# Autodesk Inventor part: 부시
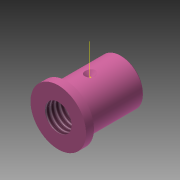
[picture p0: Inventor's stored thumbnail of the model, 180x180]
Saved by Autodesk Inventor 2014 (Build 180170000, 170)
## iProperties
Created: 2019-04
Part Number: 부시
Material: 강철, 연강
Document SubType Name: Modeling
Designer: mduedu
Density: 1 g/cm^3
Appearance: Pink
Author: mduedu
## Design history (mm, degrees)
sketch "스케치1"
  geometry: L1 (0, 0)-(3, 0); L2 (3, 0)-(3, 10.5); L3 (3, 10.5)-(0, 10.5); L4 (0, 10.5)-(0, 0); L5 (3, 0)-(24, 0); L6 (24, 0)-(24, 8.5); L7 (24, 8.5)-(3, 8.5); L8 (3, 8.5)-(3, 0)
  constraints: 16 end point, 4 parallel, 2 horizontal, 2 perpendicular
  dimensions: "d0" = 3 distance of L2.end L3.end; "d2" = 24 distance between parallel lines of L6 L4; "d3" = 17 diameter of L7 L5; "d4" = 21 diameter of L3 L1
revolve "회전1" sketch "스케치1" stored, may be unused: angle "d5" = 90 deg
sketch "스케치2"
  geometry: L1 (3, 8.5)-(24, 8.5) reference; L2 (12, 8.5)-(12, 6.5); L3 (12, 6.5)-(14, 8.5); L4 (0, -10.5)-(0, 10.5) reference; 1 further point
  constraints: 4 end point, 2 point on line, 1 perpendicular
  dimensions: "d6" = 12 distance from line of L2.start L4; "d7" = 2 distance of L2.start L3.end; "d8" = 45 deg angle of L3 L2
revolve "회전2" sketch "스케치2" stored, may be unused: angle "d9" = 90 deg
hole "구멍1" diameter "d12" = 10.106; stored, may be unused: countersink angle "d16" = 90 deg, drill point angle "d18" = 118 deg; dims "d10" = 10, "d11" = 10, "d13" = 39, "d14" = 4, "d15" = 2, "d17" = 8
chamfer "모따기1" distance "d19" = 0.5; stored, may be unused: second distance "d20" = 2, angle "d21" = 45 deg
node "작업점1"
  node "작업 평면1"
  node "작업축1"
workpoint "Work Point2"
  workaxis "Work Axis2"
node "솔리드1"
